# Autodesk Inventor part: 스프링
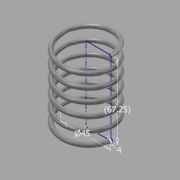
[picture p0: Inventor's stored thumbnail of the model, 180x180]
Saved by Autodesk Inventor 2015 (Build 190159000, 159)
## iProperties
Created: 2016-02
Part Number: 스프링
Material: 스테인레스 스틸
Document SubType Name: Modeling
Designer: Administrator
Mass: 84.3547 g
Surface Area: 106.584 cm^2
Volume: 10.5443 cm^3
Density: 8 g/cm^3
Appearance: 반연마
Author: Administrator
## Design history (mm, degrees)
sketch "스케치1"
  geometry: L1 (0, 67.25)-(-22.5, 67.25); L2 (-22.5, 67.25)-(-22.5, 0); L3 (-22.5, 0)-(0, 0); L4 (0, 0)-(0, 67.25); C1 r 2 at (-22.5, 0); 1 further point
  constraints: 8 end point, 2 coincident, 2 parallel, 1 centre point, 1 horizontal, 1 perpendicular
  dimensions: "d0" = 45 diameter of L2 L4; "d1" = 67.25 distance of L1.end L2.end (derived); "d2" = 4 diameter of C1
feature "코일1" sketch "스케치1" pitch "d3" = 10; turns "d5" = 6; dims "d4" = 67.25 (= d1), "d6" = 0, angle "d7" = 90 deg, angle "d8" = 90 deg, "d9" = 0, "d10" = 0
sketch "스케치2"
  geometry: L1 (20.5, 0)-(24.5, 0) reference; 1 further point
  constraints: 1 horizontal alignment
extrude "돌출1" cut sketch "스케치2" stored distance "d11" = 10; taper "d12" = 0 deg
node "작업 평면1"
sketch "스케치3"
  geometry: L1 (2, 0)-(-2, 0) reference; 1 further point
  constraints: 1 horizontal alignment
extrude "돌출2" cut sketch "스케치3" stored distance "d13" = 10; taper "d14" = 0 deg
node "솔리드1"
node "절단 모서리 투영1"
node "절단 모서리 투영2"
